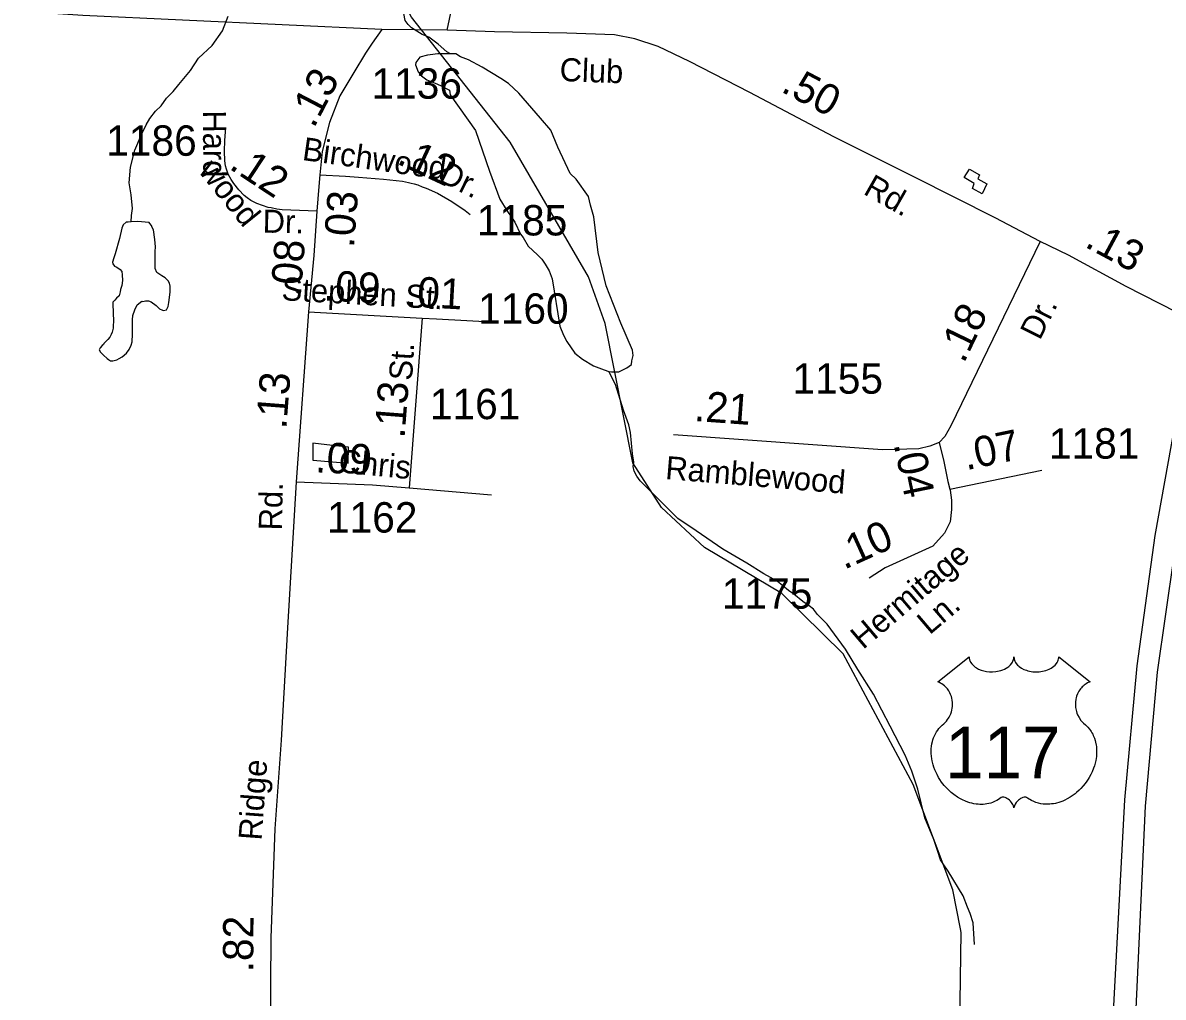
# Model space of a CAD drawing. Extents: x 2206922 to 2357709, y 510027 to 673830.
# Drawn here: x 2276310 to 2280998, y 540388 to 544394 of the extents above; entities that cross this region are included whole.
import ezdxf

# ---------------------------------------------------------------- set-up
doc = ezdxf.new("R2010")
doc.units = 0
for name, color, linetype in [('Exist Hydrographic Creek Single Shore', 7, 'Continuous'), ('Exist Hydrographic Misc Water Feature', 7, 'Continuous'), ('Exist Road Non-System Type 51', 7, 'Continuous'), ('Exist Road Primary US Divided Attributed', 7, 'Continuous'), ('Exist Road Primary US Shield CELL', 7, 'Continuous'), ('Exist Road Primary US Shield Number Label', 7, 'Continuous'), ('Exist Road Secondary Mileage Hundredths English Label', 7, 'Continuous'), ('Exist Road Secondary Type 51 Attributed', 7, 'Continuous'), ('Exist Road Secondary Type 51 Label', 7, 'Continuous'), ('Exist Road Secondary Type 51 Number Label', 7, 'Continuous')]:
    doc.layers.add(name, color=color, linetype=linetype)

msp = doc.modelspace()

# ---------------------------------------------------------------- linework, layer by layer
at = {"layer": 'Exist Hydrographic Creek Single Shore'}
for points in [[(2280164.8, 540669.7), (2280132.8, 540829.5), (2279970.8, 541262.3), (2279682.9, 541799.5), (2279430.9, 542047.2), (2279111.9, 542237.3), (2278935.9, 542401.6), (2278817.8, 542584.3), (2278703.8, 543157.3), (2278635.9, 543348.9), (2278313.8, 543903.1), (2277908.8, 544416.3), (2277722.8, 544754.5), (2277284.9, 545242.2), (2277166.7, 545441.3), (2277106.9, 545616.4), (2277042.9, 546224.4), (2276939.8, 546505.2)], [(2278492.8, 534526.4), (2279361, 536093), (2279385, 536233.5), (2279373.9, 536519), (2279270, 536957.3), (2279223.8, 537450.2), (2279247.8, 537531.7), (2279451.8, 537983.5), (2279673.9, 538320.1), (2279746.9, 538554.7), (2279753.9, 538695.6), (2279809.9, 538937.2), (2279874.9, 539103.1), (2280054.9, 539371.7), (2280127.9, 539622.7), (2280157.8, 539989.4), (2280167.9, 540655), (2280164.8, 540669.7)]]:
    msp.add_lwpolyline(points, dxfattribs=at)
at = {"layer": 'Exist Hydrographic Misc Water Feature'}
for points in [[(2278068, 544266.3), (2278054, 544274.1), (2278017.9, 544305.4), (2277979.6, 544335.2), (2277951.5, 544345.1), (2277907.6, 544372.4), (2277895.1, 544386.4), (2277882.8, 544402.5), (2277872.7, 544454.2), (2277852, 544493.9)], [(2276755.2, 543576), (2276757.1, 543602.1), (2276760.9, 543630.3), (2276756.2, 543686.2), (2276747.8, 543736), (2276753.6, 543800.1), (2276770.6, 543870.1), (2276797.9, 543934.5), (2276817.3, 543974.6), (2276833.1, 544000.6), (2276855.3, 544030.9), (2276878.9, 544052.9), (2276900.6, 544083.3), (2276928.3, 544111.5), (2276952.1, 544139.6), (2276999.2, 544198.2), (2277033.1, 544248.3), (2277088.4, 544300.7), (2277131.7, 544361.1), (2277154.9, 544421.3)], [(2278068, 544266.3), (2278056.1, 544266.1), (2278036, 544265.8), (2278016.1, 544265.6), (2277984.3, 544261.4), (2277974, 544261.3), (2277942, 544252.8), (2277926.5, 544230.8), (2277924.8, 544220.5), (2277935.1, 544192.6), (2277949, 544175.1), (2277971.2, 544159.2), (2278005.4, 544145.5), (2278027.6, 544135.7), (2278063.8, 544116.1), (2278067.5, 544098.1), (2278171.1, 543951.1), (2278228.7, 543783.8), (2278271.6, 543668.3), (2278300.1, 543622.7), (2278332.5, 543574.8), (2278356.9, 543525.3), (2278366.9, 543511.2), (2278387.4, 543475.7), (2278425.6, 543439.9), (2278443.8, 543422.2), (2278458, 543402.2), (2278474.2, 543374.2), (2278486.9, 543340.7), (2278518.4, 543146.9), (2278532.4, 543109.2), (2278546.7, 543083.1), (2278579.4, 543035.6), (2278611.5, 543011.6), (2278655.8, 542984.3), (2278699.9, 542966.7), (2278719.8, 542960.8)], [(2278719.8, 542960.8), (2278730.3, 542958.9), (2278760, 542959.3), (2278793.8, 542975.7), (2278811.9, 542989.6), (2278813.3, 543004), (2278819.1, 543025.8), (2278816.8, 543047.6), (2278768.2, 543159.2), (2278708.7, 543312.5), (2278675.5, 543450.1), (2278658.1, 543595.9), (2278643.5, 543643.9), (2278635.5, 543679.6), (2278584.5, 543751.3), (2278560.5, 543774.8), (2278509.4, 543882.2), (2278481.1, 543952.2), (2278438.3, 544001.6), (2278385.6, 544063.1), (2278349.7, 544104.6), (2278307, 544144.3), (2278275.1, 544164.1), (2278198.6, 544211.3), (2278142.4, 544240.9), (2278109.8, 544254.3), (2278090.1, 544266.2), (2278068, 544266.3)], [(2280201.5, 543792.4), (2280243.3, 543768.6), (2280235.8, 543752.8), (2280273.7, 543731.2), (2280254.2, 543690.8), (2280214, 543712.6), (2280221.6, 543732.6), (2280179.6, 543758), (2280201.5, 543792.4)], [(2276755.2, 543576), (2276743.5, 543574.1), (2276735.3, 543574.1), (2276723.4, 543563.8), (2276717.5, 543550.1), (2276708.3, 543507.7), (2276690.6, 543443.4), (2276684.7, 543427.6), (2276678.7, 543409.5), (2276681, 543403.5), (2276687.1, 543393.7), (2276697, 543389.7), (2276711.1, 543379.9), (2276717.5, 543372), (2276719.3, 543358), (2276719.7, 543334), (2276718.1, 543313.9), (2276711.5, 543297.9), (2276710.3, 543288), (2276706, 543272), (2276696.2, 543261.7), (2276688.4, 543253.6), (2276680.4, 543245.8), (2276680.8, 543237.7), (2276683, 543167.6), (2276681.4, 543148), (2276681.4, 543137.8), (2276677.5, 543121.8), (2276673.8, 543111.8), (2276667.9, 543101.8), (2276659.7, 543091.6), (2276643.9, 543075.4), (2276642, 543071.6), (2276636.1, 543067.2), (2276628.1, 543057.4), (2276624.2, 543049.1), (2276630.1, 543039.3), (2276642.6, 543027.3), (2276656.6, 543013.4), (2276662.7, 543009.6), (2276670.5, 543003.6), (2276680.8, 543003.7), (2276696.4, 543007.8), (2276706.8, 543014), (2276718.5, 543020.3), (2276736.3, 543036.3), (2276748, 543050.3), (2276756.2, 543068.5), (2276759.9, 543082.6), (2276761.8, 543114.4), (2276761.4, 543142.4), (2276761.2, 543172.4), (2276763, 543190.4), (2276770.8, 543214.4), (2276780.4, 543234.8), (2276800.3, 543248.8), (2276804.4, 543248.6), (2276814.3, 543250.8), (2276826.6, 543251), (2276838.3, 543247.2), (2276858.6, 543231.6), (2276872.3, 543217.3), (2276884.6, 543211.8), (2276888.5, 543211.6), (2276900.8, 543213.8), (2276908.6, 543227.7), (2276910.4, 543243.6), (2276915.8, 543285.8), (2276915.8, 543311.7), (2276913.5, 543323.8), (2276907.6, 543333.7), (2276895.5, 543345.6), (2276881.5, 543353.4), (2276869.6, 543361.3), (2276861.2, 543367.4), (2276855.1, 543383.4), (2276854.9, 543403.2), (2276854.7, 543437.3), (2276854.2, 543453.2), (2276856.3, 543473.2), (2276853.6, 543503.2), (2276847.5, 543543), (2276841.5, 543552.8), (2276839.5, 543560.9), (2276833.1, 543569.1), (2276829.2, 543573), (2276781.2, 543576.5), (2276755.2, 543576)], [(2280222.6, 540605.6), (2280216.5, 540694.1), (2280204.2, 540732), (2280193.9, 540757.9), (2280175.7, 540805.7), (2280114.2, 540906.9), (2280094.1, 540936.8), (2280082.4, 540952.7), (2280071.9, 540986.8), (2280055.5, 541036.3), (2280018.6, 541126.1), (2279989.3, 541243.7), (2279964.5, 541317.6), (2279938, 541383.2), (2279875.1, 541502.6), (2279807.6, 541634), (2279742.8, 541735), (2279692.2, 541818.4), (2279617.1, 541921.8), (2279576.9, 541961.5), (2279560.7, 541983.5), (2279542.5, 541997.1), (2279516.6, 542014.8), (2279480.3, 542044.6), (2279458.2, 542060.1), (2279411.9, 542097.9), (2279357.1, 542129.3), (2279287, 542172.7), (2279188.6, 542229.7), (2279077.8, 542304.8), (2279003.4, 542356.1), (2278945, 542413.6), (2278882.4, 542476.6), (2278848.2, 542510.5), (2278833.8, 542530.1), (2278823.6, 542550.3), (2278819.7, 542569.9), (2278821.5, 542587.9), (2278817, 542622.3), (2278808.6, 542709.9), (2278802, 542741.7), (2278779.3, 542801.5), (2278746.7, 542907.4), (2278719.8, 542960.8)], [(2277583.6, 542656.4), (2277503, 542665.7), (2277502, 542595.7), (2277648, 542583), (2277649.4, 542648.9), (2277583.6, 542656.4)]]:
    msp.add_lwpolyline(points, dxfattribs=at)
at = {"layer": 'Exist Road Non-System Type 51'}
for points in [[(2278010.4, 543176.7), (2278260.8, 543162.5)], [(2277898, 542482), (2278236.8, 542453.2)]]:
    msp.add_lwpolyline(points, dxfattribs=at)
at = {"layer": 'Exist Road Primary US Divided Attributed'}
for points in [[(2281123.2, 543168.4), (2280963.1, 542286.2), (2280889.6, 541750.5), (2280839.6, 541200), (2280786.6, 540225.7), (2280721.9, 538730.5), (2280668.9, 537559), (2280645.4, 537093.9), (2280624.8, 536905.5), (2280605.1, 536752.5), (2280579, 536616.1), (2280539, 536445.7), (2280451.7, 536191.7), (2280360.9, 535984.7), (2280213.6, 535718), (2280172.2, 535655.7), (2279502, 534810.1)], [(2279430.3, 534652.5), (2279800, 535100.2), (2280271.8, 535691.3), (2280304.5, 535759.9), (2280414.7, 535956.4), (2280518.9, 536179), (2280609.1, 536421.6), (2280657.2, 536602.1), (2280683.3, 536734.5), (2280710.1, 536879), (2280755.9, 537091), (2280761.4, 537542.5), (2280813.1, 538724.6), (2280851.3, 539451.6), (2280880.8, 540222.8), (2280924.9, 541173.5), (2280974.9, 541724), (2281042.5, 542200.8), (2281205.4, 543126.5)]]:
    msp.add_lwpolyline(points, dxfattribs=at)
at = {"layer": 'Exist Road Primary US Shield CELL'}
msp.add_lwpolyline([(2280200.5, 541787), (2280200.9, 541781.6), (2280202.2, 541775.3), (2280203.2, 541772.1), (2280206.1, 541765.8), (2280211, 541758.5), (2280217.8, 541751.3), (2280225.5, 541744.9), (2280230.6, 541741.6), (2280239.4, 541736.9), (2280249.3, 541732.7), (2280260.4, 541729.5), (2280271.7, 541727.2), (2280284.1, 541725.9), (2280296.3, 541725.6), (2280309.6, 541726.6), (2280324.1, 541729.4), (2280330.9, 541731.2), (2280338.4, 541733.8), (2280345.4, 541736.7), (2280353.1, 541740.8), (2280359.2, 541744.7), (2280364.1, 541748.2), (2280370.9, 541754.7), (2280376.3, 541761.5), (2280378.6, 541765.3), (2280380.6, 541769), (2280383.3, 541776.7), (2280384, 541780.1), (2280384.6, 541787.2), (2280385, 541781.3), (2280385.6, 541777.5), (2280386.6, 541773.9), (2280388.1, 541770), (2280390.9, 541764.6), (2280393.9, 541760), (2280399.6, 541753.2), (2280403.2, 541749.9), (2280406.5, 541747.2), (2280415.2, 541741.2), (2280425.4, 541736.1), (2280430.4, 541733.9), (2280435.6, 541732), (2280442.1, 541730.1), (2280448.9, 541728.5), (2280455.6, 541727.3), (2280462.4, 541726.3), (2280469.4, 541725.8), (2280475.1, 541725.6), (2280482.1, 541725.7), (2280488.5, 541726.1), (2280495.1, 541726.9), (2280502.4, 541728.1), (2280508.3, 541729.4), (2280516, 541731.4), (2280523, 541733.9), (2280529.2, 541736.6), (2280537.1, 541740.8), (2280543.6, 541744.8), (2280548.3, 541748.6), (2280553.9, 541753.8), (2280559.2, 541759.9), (2280562.4, 541764.4), (2280564.6, 541769), (2280566.6, 541773.9), (2280567.9, 541779.1), (2280568.5, 541783.5), (2280568.6, 541787.4), (2280697.2, 541684.9), (2280694.2, 541683.8), (2280687.2, 541680.4), (2280681.6, 541677.1), (2280672.8, 541670.9), (2280669, 541667.4), (2280665.2, 541663.9), (2280661.7, 541660.1), (2280658.6, 541656.5), (2280654.9, 541651.3), (2280651.6, 541646.2), (2280648.3, 541640.5), (2280645.9, 541635.5), (2280641.9, 541625.2), (2280640, 541618.7), (2280638.8, 541613.1), (2280637.3, 541601.6), (2280636.9, 541596.2), (2280636.9, 541590.8), (2280637.2, 541585.1), (2280637.8, 541579.6), (2280638.8, 541573.9), (2280639.7, 541568.9), (2280641.3, 541562.7), (2280643.5, 541555.6), (2280646.4, 541548.7), (2280652.2, 541537.5), (2280659.8, 541526.1), (2280665.2, 541519.7), (2280670.5, 541514.2), (2280678.4, 541507.6), (2280682.7, 541503.8), (2280687.7, 541498.8), (2280695.7, 541489.5), (2280699, 541485.1), (2280702.3, 541480.1), (2280705.3, 541475), (2280708.4, 541469.6), (2280710.8, 541464.8), (2280715.3, 541453.8), (2280718.6, 541443), (2280720.1, 541437.4), (2280722.5, 541424.8), (2280723.4, 541418.6), (2280724.4, 541406.3), (2280724.5, 541391.4), (2280723.3, 541377.2), (2280720.7, 541360.8), (2280718.5, 541350.9), (2280715.1, 541339.4), (2280711.8, 541329.4), (2280705.9, 541314.8), (2280700.7, 541304.1), (2280694, 541291.7), (2280689.3, 541284.2), (2280683.9, 541276.1), (2280677.2, 541266.8), (2280669.3, 541257), (2280659.8, 541246.5), (2280652.1, 541238.9), (2280642.1, 541229.9), (2280636, 541224.9), (2280627.4, 541218.4), (2280615.5, 541210.5), (2280603.8, 541203.7), (2280593.9, 541198.6), (2280585.1, 541194.8), (2280573.7, 541190.5), (2280554.7, 541185.2), (2280547.8, 541183.8), (2280539.6, 541182.6), (2280531.9, 541181.8), (2280524.5, 541181.3), (2280514.4, 541181.3), (2280504.5, 541182.1), (2280495.1, 541183.5), (2280485.3, 541185.5), (2280475, 541188.6), (2280465.7, 541192.2), (2280456.3, 541196.9), (2280440.4, 541206.9), (2280435.8, 541209.3), (2280433.2, 541210), (2280427.1, 541210.3), (2280421.3, 541209.1), (2280415.4, 541206.7), (2280411.8, 541204.8), (2280407, 541201.7), (2280403.4, 541198.8), (2280399, 541194.6), (2280396, 541191.1), (2280393.6, 541188.4), (2280389.2, 541181.3), (2280387.6, 541178), (2280385.9, 541173.7), (2280384.4, 541167.3), (2280382.4, 541175.3), (2280380, 541180.7), (2280377.3, 541185.2), (2280374.5, 541189.3), (2280370, 541194.4), (2280366, 541198.3), (2280361.1, 541202.2), (2280355.9, 541205.4), (2280351.8, 541207.5), (2280348, 541208.9), (2280343.4, 541210.1), (2280339.6, 541210.4), (2280336.5, 541210.3), (2280332.2, 541209.3), (2280326.3, 541205.1), (2280320.8, 541201.3), (2280314.8, 541197.6), (2280307.7, 541193.8), (2280302.5, 541191.4), (2280296.2, 541188.9), (2280288.9, 541186.5), (2280281, 541184.5), (2280272.9, 541182.9), (2280265.8, 541181.7), (2280258.1, 541181), (2280251.2, 541180.8), (2280244, 541180.9), (2280237.2, 541181.4), (2280229.4, 541182.1), (2280219.7, 541183.6), (2280211.6, 541185.4), (2280203.1, 541187.7), (2280194.4, 541190.4), (2280185.1, 541194), (2280173.4, 541199.1), (2280165.2, 541203.2), (2280152.4, 541210.6), (2280137.4, 541221), (2280126, 541230.2), (2280117.7, 541237.7), (2280105.5, 541250.2), (2280098.3, 541258.3), (2280087, 541272.9), (2280079.8, 541283.5), (2280075.1, 541291.2), (2280068.3, 541303.7), (2280064.5, 541311.5), (2280059.7, 541322.9), (2280055.8, 541333.3), (2280052.6, 541343.2), (2280050.9, 541349.5), (2280048.5, 541360.5), (2280047, 541368.3), (2280045.6, 541379.1), (2280044.8, 541390.4), (2280044.6, 541400.8), (2280044.9, 541409.5), (2280045.9, 541419.6), (2280047.6, 541430.3), (2280049.6, 541439.5), (2280051.5, 541446.1), (2280054.2, 541454.1), (2280057.8, 541463), (2280062.1, 541471.5), (2280066.2, 541478.6), (2280071.2, 541486.2), (2280076.3, 541492.7), (2280082.8, 541499.8), (2280089.7, 541506.3), (2280095.9, 541511.4), (2280103.4, 541518.7), (2280107.2, 541523.1), (2280111.9, 541529.3), (2280115.6, 541535), (2280118.6, 541540.1), (2280122.5, 541547.6), (2280124.9, 541553.2), (2280127.8, 541561.9), (2280129.3, 541568), (2280130.8, 541575.8), (2280131.8, 541583.2), (2280132.2, 541592.4), (2280132, 541600), (2280131, 541608.8), (2280129.3, 541617.4), (2280127.3, 541624.8), (2280124.1, 541633.3), (2280121.2, 541639.5), (2280116.3, 541648), (2280110.8, 541655.8), (2280105.1, 541662.2), (2280099.4, 541667.9), (2280094, 541672.1), (2280088.8, 541675.9), (2280082.2, 541679.8), (2280075.9, 541682.9), (2280072, 541684.5)], close=True, dxfattribs=at)
at = {"layer": 'Exist Road Secondary Type 51 Attributed'}
for p, q in [((2278055.1, 544362.8), (2277786.7, 544366.2)), ((2277485.4, 543205.8), (2277434.5, 542507.5)), ((2280121.3, 542476.3), (2280499.1, 542555.2))]:
    msp.add_line(p, q, dxfattribs=at)
for points in [[(2278055.1, 544362.8), (2278118, 544661.9), (2278142.6, 544804.1), (2278147.8, 544918.8), (2278141, 545013.2), (2278116, 545109.8), (2278058.6, 545306.9), (2278025.1, 545419.6), (2277949, 545647.9), (2277824.2, 546037.7), (2277787.7, 546180.8), (2277769.5, 546336.1), (2277787.2, 546465.8), (2277818.4, 546548.1), (2277867.5, 546660.5), (2277920.7, 546740.8), (2278011.2, 546877.7), (2278133.4, 547070.8), (2278273.4, 547279.9), (2278321.2, 547349.6), (2278350.1, 547412.5), (2278458, 547645)], [(2277786.7, 544366.2), (2276557.1, 544423.4), (2276331.1, 544439.3), (2276239.2, 544438.4), (2276181.2, 544437.8), (2276135.3, 544423.5), (2276083.5, 544404.9), (2276047.9, 544372.7), (2276014.1, 544352.4), (2275951.1, 544239.9), (2275800.4, 543904.6), (2275642, 543535.2), (2275535, 543232.5), (2275461.1, 543001.8), (2275393.2, 542775.3), (2275367.7, 542727.2), (2275272.5, 542444.5), (2275192.3, 542251.8), (2275133.6, 542123.4), (2275055.7, 541900.6), (2274946.7, 541589.8), (2274841.5, 541281), (2274790.9, 541154.7)], [(2277786.7, 544366.2), (2277746.8, 544309.5), (2277719.5, 544268.6), (2277670.6, 544189.7), (2277613.6, 544092.9), (2277571.4, 543983.7), (2277541.6, 543864.6), (2277531.7, 543768.4)], [(2280491.8, 543494.9), (2280307.9, 543592.2), (2279975.8, 543759.3), (2279644.1, 543925.3), (2279298.6, 544107.3), (2279051, 544234.5), (2278921.5, 544295.9), (2278826.1, 544327.7), (2278742, 544343.6), (2278546.6, 544350.4), (2278249, 544357.2), (2278055.1, 544362.8)], [(2277519.7, 543619.9), (2277376.3, 543624.2), (2277354.7, 543627.3), (2277331.7, 543632.6), (2277319.3, 543635.1), (2277273, 543651.2), (2277247.4, 543663.5), (2277232.6, 543673.6), (2277220.3, 543684), (2277198.9, 543707.3), (2277177.5, 543733.8), (2277167.5, 543750), (2277155.2, 543771.6), (2277147.8, 543791.9), (2277143, 543806.1), (2277141, 543826.4), (2277139.7, 543866.2), (2277140.3, 543909.4), (2277145, 543963.4)], [(2277531.7, 543768.4), (2277526.8, 543720.6), (2277519.7, 543619.9)], [(2277531.7, 543768.4), (2277636.5, 543762.8), (2277689.9, 543758.7), (2277792.6, 543750.5), (2277870.5, 543742.9), (2277884, 543740.1), (2277896.2, 543737.7), (2277906.5, 543734.4), (2277918.6, 543731.2), (2277934, 543727), (2277951.8, 543719.5), (2277968.1, 543713.9), (2278014.4, 543692.9), (2278074.4, 543658.9), (2278129.4, 543622), (2278150, 543606.3)], [(2277519.7, 543619.9), (2277506.9, 543437.7), (2277485.4, 543205.8)], [(2280491.8, 543494.9), (2280125.1, 542736.7), (2280100.8, 542693.5), (2280077.3, 542669)], [(2281123.2, 543168.4), (2280845.4, 543310.3), (2280608.2, 543438), (2280491.8, 543494.9)], [(2277485.4, 543205.8), (2277951.7, 543180)], [(2277951.7, 543180), (2277898, 542482)], [(2277951.7, 543180), (2278010.4, 543176.7)], [(2280077.3, 542669), (2280038.7, 542653), (2279994, 542643), (2279844, 542638.5), (2278984.5, 542700.7)], [(2280077.3, 542669), (2280096.2, 542590.7), (2280113.4, 542508), (2280121.3, 542476.3)], [(2277434.5, 542507.5), (2277398.4, 541906.7), (2277372.7, 541444.8), (2277346.2, 541080.7), (2277330.4, 540632.8), (2277326.8, 540252.9), (2277326.4, 540215), (2277325, 539727.2), (2277333.5, 539229.7), (2277334.8, 538895.8), (2277331.8, 538574), (2277331.5, 538394), (2277325.4, 538193.7)], [(2277434.5, 542507.5), (2277748.2, 542494.9), (2277898, 542482)], [(2280121.3, 542476.3), (2280122.2, 542472.7), (2280128.1, 542431.4), (2280128.1, 542393.1), (2280122.2, 542343), (2280098.7, 542295.9), (2280051.5, 542242.8), (2279854.7, 542153.7), (2279789.2, 542111)]]:
    msp.add_lwpolyline(points, dxfattribs=at)

# ---------------------------------------------------------------- texts
at = {"layer": 'Exist Road Primary US Shield Number Label'}
msp.add_text('117', height=212.5, dxfattribs=at).set_placement((2280101.7, 541287.7))
at = {"layer": 'Exist Road Secondary Mileage Hundredths English Label'}
for s, rotation, p in [('.13', 62.4634, (2277506.8, 543956.8)), ('.50', 332.2117, (2279422.3, 544112.8)), ('.12', 334.9584, (2277843.1, 543816.8)), ('.12', 326.6206, (2277154.1, 543796.6)), ('.03', 85.6005, (2277671.3, 543467)), ('.13', 331.7037, (2280670.9, 543475.2)), ('.08', 85.6005, (2277453.1, 543266.7)), ('.09', 356.832, (2277545.1, 543252.6)), ('.01', 356.832, (2277882.6, 543228.2)), ('.18', 64.1879, (2280178.4, 542990.4)), ('.13', 85.6005, (2277393.3, 542721.6)), ('.13', 85.6005, (2277879.3, 542683.6)), ('.21', 355.8603, (2279067.7, 542757.3)), ('.07', 11.7958, (2280188.3, 542554.1)), ('.09', 357.3109, (2277510.6, 542546.1)), ('.04', 281.72, (2279890, 542661.6)), ('.10', 24.3611, (2279686.4, 542144.4)), ('.82', 89.6768, (2277257.6, 540490.4))]:
    msp.add_text(s, height=125, rotation=rotation, dxfattribs=at).set_placement(p)
at = {"layer": 'Exist Road Secondary Type 51 Label'}
for s, rotation, p in [('Club', 357.8688, (2278515.8, 544154.6)), ('Hard', 270.4115, (2277050.7, 544033.4)), ('Birchwood', 352.0092, (2277455.9, 543830.1)), ('wood', 308.945, (2277029, 543783.4)), ('Dr.', 333.84, (2278014.5, 543743.9)), ('Rd.', 330.4128, (2279761, 543692.2)), ('Dr.', 359.0287, (2277295.8, 543531)), ('Stephen St.', 356.7133, (2277372.6, 543253.8)), ('Dr.', 63.2399, (2280490.5, 543085.4)), ('St.', 86.4799, (2277910.2, 542921.3)), ('Chris', 354.5337, (2277605.7, 542546.1)), ('Ramblewood', 355.3072, (2278949.2, 542518.5)), ('Rd.', 88.6162, (2277374.9, 542306.3)), ('Hermitage', 40.3926, (2279764.3, 541815.1)), ('Ln.', 40.3926, (2280037.8, 541875.4)), ('Ridge', 85.8373, (2277291.7, 541031.1))]:
    msp.add_text(s, height=95, rotation=rotation, dxfattribs=at).set_placement(p)
at = {"layer": 'Exist Road Secondary Type 51 Number Label'}
for s, p in [('1136', (2277743.7, 544081.7)), ('1186', (2276653.4, 543847.1)), ('1185', (2278176.7, 543519.6)), ('1160', (2278182.2, 543156.7)), ('1155', (2279474.4, 542869.2)), ('1161', (2277983.7, 542764.4)), ('1181', (2280528.3, 542602.3)), ('1162', (2277560.7, 542298.3)), ('1175', (2279184, 541985.2))]:
    msp.add_text(s, height=125, dxfattribs=at).set_placement(p)

doc.saveas('drawing.dxf')
